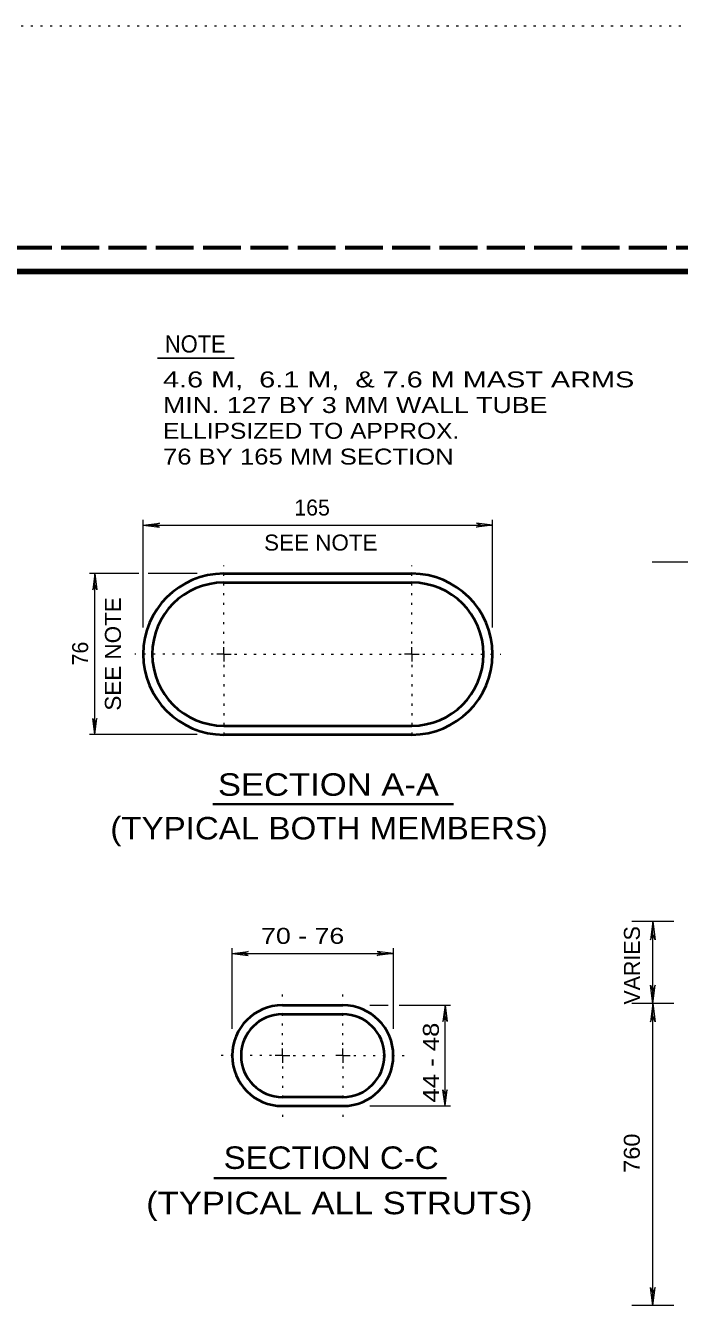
# Model space of a CAD drawing. Extents: x 312583 to 312854, y 144419 to 144597.
# Drawn here: x 312695.3 to 312726.3, y 144535.4 to 144596.8 of the extents above; entities that cross this region are included whole.
import ezdxf
from ezdxf.enums import TextEntityAlignment as Align

# ---------------------------------------------------------------- set-up
doc = ezdxf.new("R2010")
doc.units = 0
doc.header["$LTSCALE"] = 0.3
for name, pattern in [('DOTTED', [1.5, 0.3, -1.2]), ('LONG_DASH_SHORT_DASH', [9.9, 6, -1.2, 1.5, -1.2]), ('LONG_DASHED', [7.5, 6, -1.5])]:
    doc.linetypes.add(name, pattern=pattern)
for name, color, linetype, lineweight in [('1', 7, 'Continuous', 40), ('62', 7, 'DOTTED', 13), ('63', 7, 'LONG_DASHED', 60)]:
    doc.layers.add(name, color=color, linetype=linetype, lineweight=lineweight)

msp = doc.modelspace()

# ---------------------------------------------------------------- linework, layer by layer
at = {"layer": '1', "lineweight": 25}
msp.add_line((312701.5246, 144580.9747), (312705.1816, 144580.9747), dxfattribs=at)
at = {"layer": '1', "lineweight": 13}
for p, q in [((312700.8499, 144568.156), (312700.8499, 144573.2697)), ((312700.8499, 144573.0167), (312701.6242, 144573.1087)), ((312700.8499, 144573.0167), (312717.4636, 144573.0167)), ((312700.8499, 144573.0167), (312701.6242, 144572.917)), ((312701.6242, 144573.1087), (312701.3789, 144573.0167)), ((312701.6242, 144572.917), (312701.3789, 144573.0167)), ((312716.6969, 144573.1087), (312716.9422, 144573.0167)), ((312717.4636, 144573.0167), (312716.6969, 144573.1087)), ((312716.6969, 144572.917), (312716.9422, 144573.0167)), ((312717.4636, 144573.0167), (312716.6969, 144572.917)), ((312717.4636, 144568.156), (312717.4636, 144573.2697)), ((312700.6506, 144570.7167), (312698.2969, 144570.7167)), ((312698.5499, 144570.7167), (312698.4579, 144569.9423)), ((312698.5499, 144563.05), (312698.5499, 144570.7167)), ((312698.5499, 144570.7167), (312698.6496, 144569.9423)), ((312703.4106, 144570.7167), (312701.0876, 144570.7167)), ((312698.4579, 144569.9423), (312698.5499, 144570.1877)), ((312698.6496, 144569.9423), (312698.5499, 144570.1877)), ((312704.6832, 144566.8833), (312704.3459, 144566.8833)), ((312704.6832, 144566.8833), (312704.6832, 144567.2207)), ((312704.6832, 144566.8833), (312705.0282, 144566.8833)), ((312704.6832, 144566.8833), (312704.6832, 144566.5383)), ((312713.6302, 144566.8833), (312713.2852, 144566.8833)), ((312713.6302, 144566.8833), (312713.6302, 144567.2207)), ((312713.6302, 144566.8833), (312713.9752, 144566.8833)), ((312713.6302, 144566.8833), (312713.6302, 144566.5383)), ((312698.4579, 144563.8167), (312698.5499, 144563.5713)), ((312698.5499, 144563.05), (312698.4579, 144563.8167)), ((312698.6496, 144563.8167), (312698.5499, 144563.5713)), ((312698.5499, 144563.05), (312698.6496, 144563.8167)), ((312703.4106, 144563.05), (312698.2969, 144563.05)), ((312726.0852, 144554.1508), (312724.0869, 144554.1508)), ((312725.0916, 144554.1508), (312724.9843, 144553.2845)), ((312725.0916, 144550.2562), (312725.0916, 144554.1508)), ((312725.0916, 144554.1508), (312725.1989, 144553.2845)), ((312724.9843, 144553.2845), (312725.0916, 144553.5605)), ((312725.1989, 144553.2845), (312725.0916, 144553.5605)), ((312705.0819, 144549.0506), (312705.0819, 144552.8839)), ((312705.0819, 144552.6309), (312705.8486, 144552.7229)), ((312705.8486, 144552.7229), (312705.6032, 144552.6309)), ((312711.9742, 144552.7229), (312712.2196, 144552.6309)), ((312712.7486, 144552.6309), (312711.9742, 144552.7229)), ((312712.7486, 144549.0506), (312712.7486, 144552.8839)), ((312705.0819, 144552.6309), (312712.7486, 144552.6309)), ((312705.0819, 144552.6309), (312705.8486, 144552.5389)), ((312705.8486, 144552.5389), (312705.6032, 144552.6309)), ((312711.9742, 144552.5389), (312712.2196, 144552.6309)), ((312712.7486, 144552.6309), (312711.9742, 144552.5389)), ((312724.9843, 144551.1225), (312725.0916, 144550.8465)), ((312725.0916, 144550.2562), (312724.9843, 144551.1225)), ((312725.1989, 144551.1225), (312725.0916, 144550.8465)), ((312725.0916, 144550.2562), (312725.1989, 144551.1225)), ((312726.0852, 144550.2562), (312724.0869, 144550.2562)), ((312725.0916, 144550.2562), (312724.9843, 144549.3898)), ((312725.0916, 144535.8812), (312725.0916, 144550.2562)), ((312725.0916, 144550.2562), (312725.1989, 144549.3898)), ((312711.6292, 144550.1699), (312712.5032, 144550.1699)), ((312713.0246, 144550.1699), (312715.4626, 144550.1699)), ((312715.2096, 144550.1699), (312715.1099, 144549.4032)), ((312715.1099, 144549.4032), (312715.2096, 144549.6486)), ((312715.2096, 144545.3782), (312715.2096, 144550.1699)), ((312715.2096, 144550.1699), (312715.3016, 144549.4032)), ((312715.3016, 144549.4032), (312715.2096, 144549.6486)), ((312724.9843, 144549.3898), (312725.0916, 144549.6658)), ((312725.1989, 144549.3898), (312725.0916, 144549.6658)), ((312707.4739, 144547.7779), (312707.1289, 144547.7779)), ((312707.4739, 144547.7779), (312707.4739, 144548.1152)), ((312707.4739, 144547.7779), (312707.8189, 144547.7779)), ((312707.4739, 144547.7779), (312707.4739, 144547.4329)), ((312710.3489, 144547.7779), (312710.0116, 144547.7779)), ((312710.3489, 144547.7779), (312710.3489, 144548.1152)), ((312710.3489, 144547.7779), (312710.6939, 144547.7779)), ((312710.3489, 144547.7779), (312710.3489, 144547.4329)), ((312715.1099, 144546.1526), (312715.2096, 144545.9072)), ((312715.2096, 144545.3782), (312715.1099, 144546.1526)), ((312715.3016, 144546.1526), (312715.2096, 144545.9072)), ((312715.2096, 144545.3782), (312715.3016, 144546.1526)), ((312711.6292, 144545.3782), (312715.4626, 144545.3782)), ((312724.9843, 144536.7475), (312725.0916, 144536.4715)), ((312725.0916, 144535.8812), (312724.9843, 144536.7475)), ((312725.1989, 144536.7475), (312725.0916, 144536.4715)), ((312725.0916, 144535.8812), (312725.1989, 144536.7475)), ((312726.0852, 144535.8812), (312724.0869, 144535.8812))]:
    msp.add_line(p, q, dxfattribs=at)
at = {"layer": '1', "linetype": 'DOTTED', "lineweight": 13}
for p, q in [((312704.6832, 144567.3893), (312704.6832, 144571.1077)), ((312713.6302, 144567.3893), (312713.6302, 144571.1077)), ((312704.1772, 144566.8833), (312700.4589, 144566.8833)), ((312705.1969, 144566.8833), (312713.1242, 144566.8833)), ((312714.1439, 144566.8833), (312717.8622, 144566.8833)), ((312704.6832, 144566.3697), (312704.6832, 144562.728)), ((312713.6302, 144566.3697), (312713.6302, 144562.728)), ((312707.4739, 144548.2839), (312707.4739, 144550.8599)), ((312710.3489, 144548.2839), (312710.3489, 144550.8599)), ((312706.9602, 144547.7779), (312704.3536, 144547.7779)), ((312707.9876, 144547.7779), (312709.8046, 144547.7779)), ((312710.8626, 144547.7779), (312713.3772, 144547.7779)), ((312707.4739, 144547.2642), (312707.4739, 144544.5809)), ((312710.3489, 144547.2642), (312710.3489, 144544.5809))]:
    msp.add_line(p, q, dxfattribs=at)
at = {"layer": '1', "linetype": 'LONG_DASH_SHORT_DASH', "lineweight": 13}
msp.add_line((312725.0655, 144571.2705), (312846.1375, 144571.2705), dxfattribs=at)
at = {"layer": '1'}
for p, q in [((312704.6832, 144570.7167), (312713.6302, 144570.7167)), ((312704.6832, 144570.2873), (312713.6302, 144570.2873)), ((312704.6832, 144563.4717), (312713.6302, 144563.4717)), ((312704.6832, 144563.05), (312713.6302, 144563.05)), ((312707.4739, 144550.1699), (312710.3489, 144550.1699)), ((312707.4739, 144549.7482), (312710.3489, 144549.7482)), ((312707.4739, 144545.8076), (312710.3489, 144545.8076)), ((312707.4739, 144545.3782), (312710.3489, 144545.3782))]:
    msp.add_line(p, q, dxfattribs=at)
at = {"layer": '1', "lineweight": 35}
for p, q in [((312704.1579, 144559.7446), (312715.6035, 144559.7446)), ((312704.2154, 144541.9512), (312715.2712, 144541.9512))]:
    msp.add_line(p, q, dxfattribs=at)
at = {"layer": '1', "lineweight": 158}
msp.add_lwpolyline([(312616.5, 144423.1446), (312616.5, 144585.0846), (312849, 144585.0846)], dxfattribs=at)
at = {"layer": '1'}
for centre, radius, start, end in [((312704.6858, 144566.8808), 3.8333, 90, 270), ((312713.6302, 144566.8808), 3.8333, 270, 90), ((312704.6858, 144566.8808), 3.4066, 90, 270), ((312713.6302, 144566.8808), 3.4066, 270, 90), ((312707.4739, 144547.7753), 2.3958, 90, 270), ((312707.4739, 144547.7753), 1.9699, 90, 270), ((312710.3515, 144547.7753), 2.3958, 270, 90), ((312710.3515, 144547.7753), 1.9699, 270, 90)]:
    msp.add_arc(centre, radius, start, end, dxfattribs=at)
at = {"layer": '62'}
msp.add_line((312601.2, 144596.7846), (312853.5, 144596.7846), dxfattribs=at)
at = {"layer": '63'}
msp.add_line((312851.75, 144586.2246), (312583.526, 144586.2246), dxfattribs=at)

# ---------------------------------------------------------------- texts
at = {"layer": '1'}
for s, height, width, p in [('NOTE', 0.8177, 0.95, (312703.3262, 144581.2353)), ('SECTION A-A', 1.07, 1.15, (312709.661, 144560.1421)), ('(TYPICAL BOTH MEMBERS)', 1.07, 1.1, (312709.6928, 144558.0631)), ('SECTION C-C', 1.07, 1.1, (312709.7903, 144542.3843)), ('(TYPICAL ALL STRUTS)', 1.07, 1.15, (312710.1815, 144540.2265))]:
    msp.add_text(s, height=height, dxfattribs=dict(at, width=width)).set_placement(p, align=Align.CENTER)
for s, width, p in [('4.6 M,  6.1 M,  & 7.6 M MAST ARMS', 1.35, (312701.7929, 144579.5757)), ('MIN. 127 BY 3 MM WALL TUBE', 1.25, (312701.7929, 144578.3567)), ('ELLIPSIZED TO APPROX.', 1.15, (312701.7929, 144577.13)), ('76 BY 165 MM SECTION', 1.2, (312701.7929, 144575.9034)), ('SEE NOTE', 1.05, (312706.5999, 144571.8123)), ('70 - 76', 1.25, (312706.4584, 144553.0947))]:
    msp.add_text(s, height=0.76, dxfattribs=dict(at, width=width)).set_placement(p)
msp.add_text('165', height=0.76, dxfattribs=at).set_placement((312708.0345, 144573.4786))
for s, width, p in [('SEE NOTE', 1.05, (312699.7897, 144564.1934)), ('44 - 48', 1.2, (312714.914, 144545.5458)), ('760', 1.1, (312724.4703, 144542.2012))]:
    msp.add_text(s, height=0.76, rotation=90, dxfattribs=dict(at, width=width)).set_placement(p)
for s, p in [('76', (312698.2304, 144566.3455)), ('VARIES', (312724.4762, 144550.2069))]:
    msp.add_text(s, height=0.76, rotation=90, dxfattribs=at).set_placement(p)

doc.saveas('drawing.dxf')
